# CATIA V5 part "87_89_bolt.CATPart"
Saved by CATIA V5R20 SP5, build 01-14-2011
Part number: 87_89_bolt
Bounding box of the stored display mesh (mm): x -11 to 11, y 22.409 to 44.315, z -55.294 to -34.294
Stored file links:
  C:\Documents and Settings\anizard\Bureau\13\87_89_bolt.CATPart
  C:\Documents and Settings\anizard\Bureau\13\anizard.CATProduct
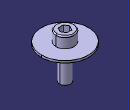
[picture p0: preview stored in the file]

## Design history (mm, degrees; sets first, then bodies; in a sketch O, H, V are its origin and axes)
Set1
  Point1: linked copy from another document
  Plane1: linked copy from another document
Body1 (main body)
  Sketch1 on Plane1, origin (0, 0, -40.2938), H (1, 0, 0), V (0, -1, 0)
    circle A1 centre (0, -33.3619) radius 2.5
    reference projected point E1 (0, -33.3619) from Point1
    radius A1 = 2.5
    concentricity: E1 A1
  Pad1: profile Sketch1, direction (0, 0, -1), length 15
  Sketch2 on start face of Pad1, origin (0, 0, -40.2938), H (1, 0, 0), V (0, -1, 0)
    circle A1 centre (0, -33.3619) radius 11
    reference projected circle E1 centre (0, -33.3619) radius 2.5 from edge [start face of Pad1 | face of Pad1 from Sketch1.A1]
    radius A1 = 11
    concentricity: A1 E1
  Pad2: profile Sketch2, direction (0, 0, 1), length 1
  Sketch3 on end face of Pad2, origin (0, 0, -39.2938), H (1, 0, 0), V (0, 1, 0)
    circle A1 centre (0, 33.3619) radius 4.25
    reference projected circle E1 centre (0, 33.3619) radius 11 from edge [end face of Pad2 | face of Pad2 from Sketch2.A1]
    radius A1 = 4.25
    concentricity: A1 E1
  Pad3: profile Sketch3, direction (0, 0, 1), length 5
  Sketch4 on end face of Pad3, origin (0, 0, -34.2938), H (1, 0, 0), V (0, 1, 0)
    point P1 (0, 33.3619)
    point P2 (1.1547, 31.3619)
    point P3 (2.3094, 33.3619)
    point P4 (1.1547, 35.3619)
    point P5 (-1.1547, 35.3619)
    point P6 (-2.3094, 33.3619)
    point P7 (-1.1547, 31.3619)
    point P8 (1.7321, 32.3619)
    line L1 (1.1547, 31.3619) -> (2.3094, 33.3619)
    line L2 (2.3094, 33.3619) -> (1.1547, 35.3619)
    line L3 (1.1547, 35.3619) -> (-1.1547, 35.3619)
    line L4 (-1.1547, 35.3619) -> (-2.3094, 33.3619)
    line L5 (-2.3094, 33.3619) -> (-1.1547, 31.3619)
    line L6 (-1.1547, 31.3619) -> (1.1547, 31.3619)
    construction line L7 (0, 33.3619) -> (1.7321, 32.3619)
    construction circle A1 centre (0, 33.3619) radius 2.3094
    construction arc A2 centre (-2.3094, 33.3619) radius 2.3094 from (-1.1547, 35.3619) to (-1.1547, 31.3619) cw
    construction arc A3 centre (2.3094, 33.3619) radius 2.3094 from (1.1547, 35.3619) to (1.1547, 31.3619) ccw
    reference projected circle E1 centre (0, 33.3619) radius 4.25 from edge [face of Pad3 from Sketch3.A1 | end face of Pad3]
    distance L5 L2 = 4
    coincidence: A1 P2, A1 P3, A1 P4, A1 P5, A1 P6, A1 P7, A2 P1, A3 P1
    midpoint: P8 L1
    parallelism: L1 L4
    concentricity: A1 E1
    horizontal: L3 H
  Pocket1: profile Sketch4, direction (0, 0, -1), length 4
  Fillet1: radius 0.5, on edge [face of Pad3 from Sketch3.A1 | end face of Pad3]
